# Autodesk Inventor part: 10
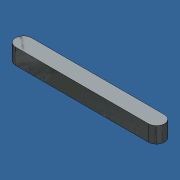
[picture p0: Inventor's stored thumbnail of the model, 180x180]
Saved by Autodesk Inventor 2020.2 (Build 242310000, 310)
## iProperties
Created: 2016-09
Part Number: 10
Material: Steel
Document SubType Name: Modeling
Designer: Mike Taylor
Mass: 15.4617 g
Surface Area: 13.6965 cm^2
Volume: 1.96965 cm^3
Density: 7.85 g/cm^3
Appearance: Plate
Translation Standard: STEP AP214IS
FileName: 29_5060_0_1.stp
PreProcessor: ACIS
PostProcessor: Build: 160, Release: 2012 RTM - Date: Tue 03/01/2011
Sent Units: centimeter
Uncertainty: 0.0
Author: Mike Taylor
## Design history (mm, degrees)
node "101"
node "10"
node "Base1"
